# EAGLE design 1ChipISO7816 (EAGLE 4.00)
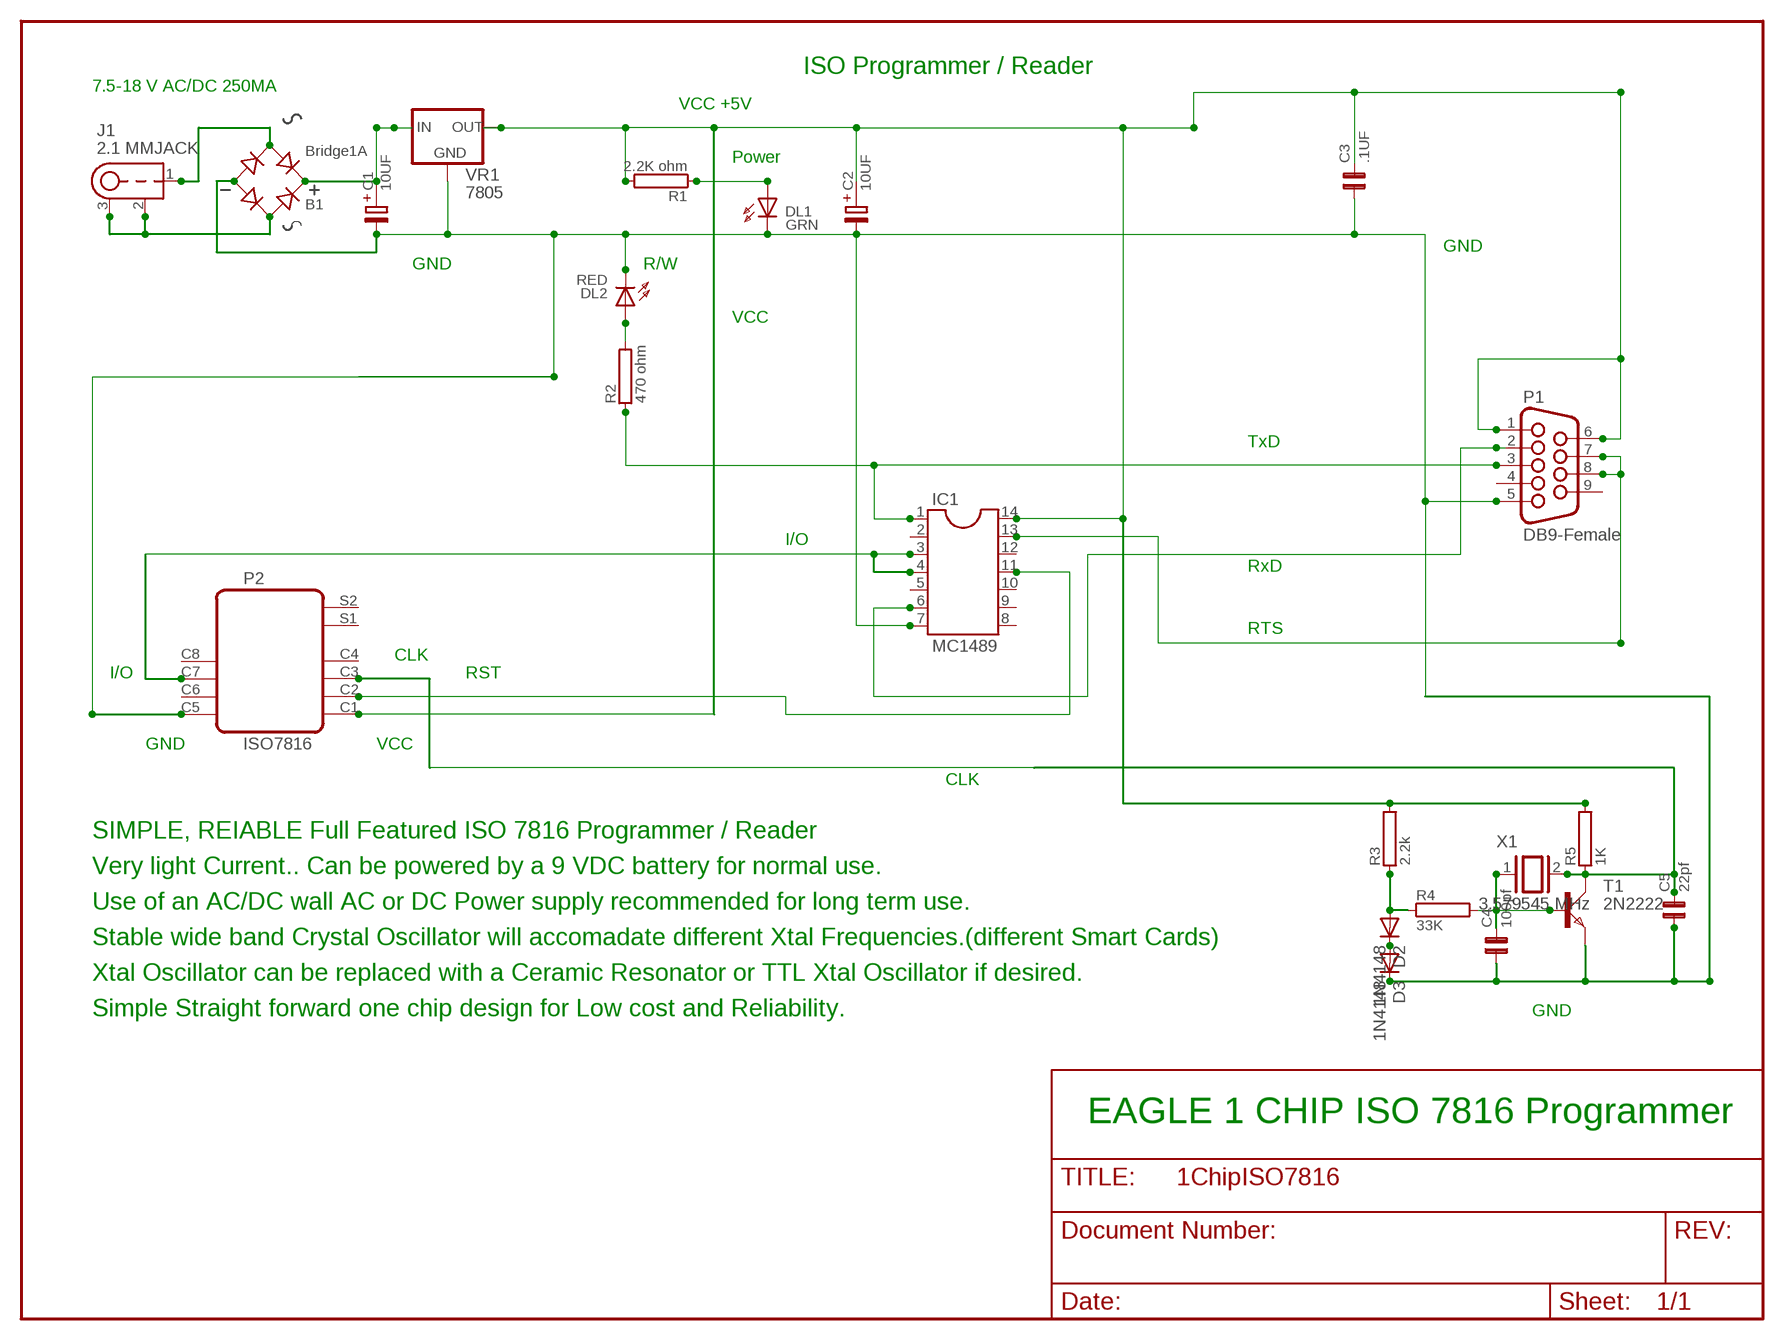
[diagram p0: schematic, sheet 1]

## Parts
B1  Bridge1A  B-DIL  [B-DIL]
C1  10UF  P128-35  [P128-35]
C2  10UF  P128-35  [P128-35]
C3  .1UF  C2,5  [C2,5-4]
C4  100pf  C2,5  [C2,5-4]
C5  22pf  C2,5  [C2,5-4]
D2  1N4148  [DO35-10]
D3  1N4148  [DO35-10]
DL1  GRN  LED5  [LED5]
DL2  RED  LED5  [LED5]
IC1  MC1489  DIL14  [DIL14]
J1  2.1 MMJACK  2MMJACK  [255SB]
P1  DB9-Female  F09H  [F09H]
P2  ISO7816  14P  [14P]
R1  2.2K ohm  0309/10@2  [0309/10@2]
R2  470 ohm  0309/10@2  [0309/10@2]
R3  2.2k  0309/10@2  [0309/10@2]
R4  33K  0309/10  [0309/10]
R5  1K  0309/10@2  [0309/10@2]
T1  2N2222  [TO18A]
VR1  7805  78XXL  [78XXL]
X1  3.579545 MHz  XTAL  [Q]

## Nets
+12V: B1.+ C1.+ VR1.E(IN)
CLK: C5.2 P2.C3 R5.1 T1.C X1.2
I/O: IC1.3 IC1.4 P2.C7
N$1: B1.- C1.- C2.- C3.1 C4.1 C5.1 D3.K(C) DL1.K DL2.K IC1.7 P1.5 P2.C5 T1.E VR1.GND
N$2: B1.AC1 J1.2 J1.3
N$3: D2.A R3.1 R4.1
N$4: IC1.6 P1.2
N$6: IC1.13 P1.7 P1.8
N$8: IC1.1 P1.3 R2.1
N$9: D2.K(C) D3.A
N$22: DL1.A R1.1
N$24: DL2.A R2.2
N$25: C4.2 R4.2 T1.B X1.1
N$28: B1.AC2 J1.1
OUT: C2.+ C3.2 IC1.14 P1.1 P1.6 P2.C1 R1.2 R3.2 R5.2 VR1.A(OUT)
RST: IC1.11 P2.C2
Unconnected: IC1.2 IC1.5 IC1.8 IC1.9 IC1.10 IC1.12 P1.4 P1.9 P2.C4 P2.C6 P2.C8 P2.S1 P2.S2

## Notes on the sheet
- ISO Programmer / Reader
- 7.5-18 V AC/DC 250MA
- VCC +5V
- Power
- GND
- GND | R/W
- VCC
- TxD
- I/O
- RxD
- RTS
- CLK
- I/O | RST
- GND | VCC
- CLK
- SIMPLE, REIABLE Full Featured ISO 7816 Programmer / Reader
- Very light Current.. Can be powered by a 9 VDC battery for normal use.
- Use of an AC/DC wall AC or DC Power supply recommended for long term use.
- Stable wide band Crystal Oscillator will accomadate different Xtal Frequencies.(different Smart Cards)
- Xtal Oscillator can be replaced with a Ceramic Resonator or TTL Xtal Oscillator if desired.
- Simple Straight forward one chip design for Low cost and Reliability. | GND
- EAGLE 1 CHIP ISO 7816 Programmer

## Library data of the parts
B1 = RECTIF:B-DIL
C1 C2 = CAP-TANT:P128-35
C3-C5 = CAP:C2,5
D2 D3 = diode:1N4148: DIODE
DL1 DL2 = LED:LED5
IC1 = dil:DIL14: SOCKET DIL14
J1 = PWRJACK:2MMJACK
P1 = D-SUB:F09H
P2 = CON-ISO:14P
R1-R3 R5 = R:0309/10@2
R4 = R:0309/10
T1 = transistor-small-signal:2N2222: NPN TRANSISTOR
VR1 = V-REG:78XXL
X1 = SPECIAL:XTAL

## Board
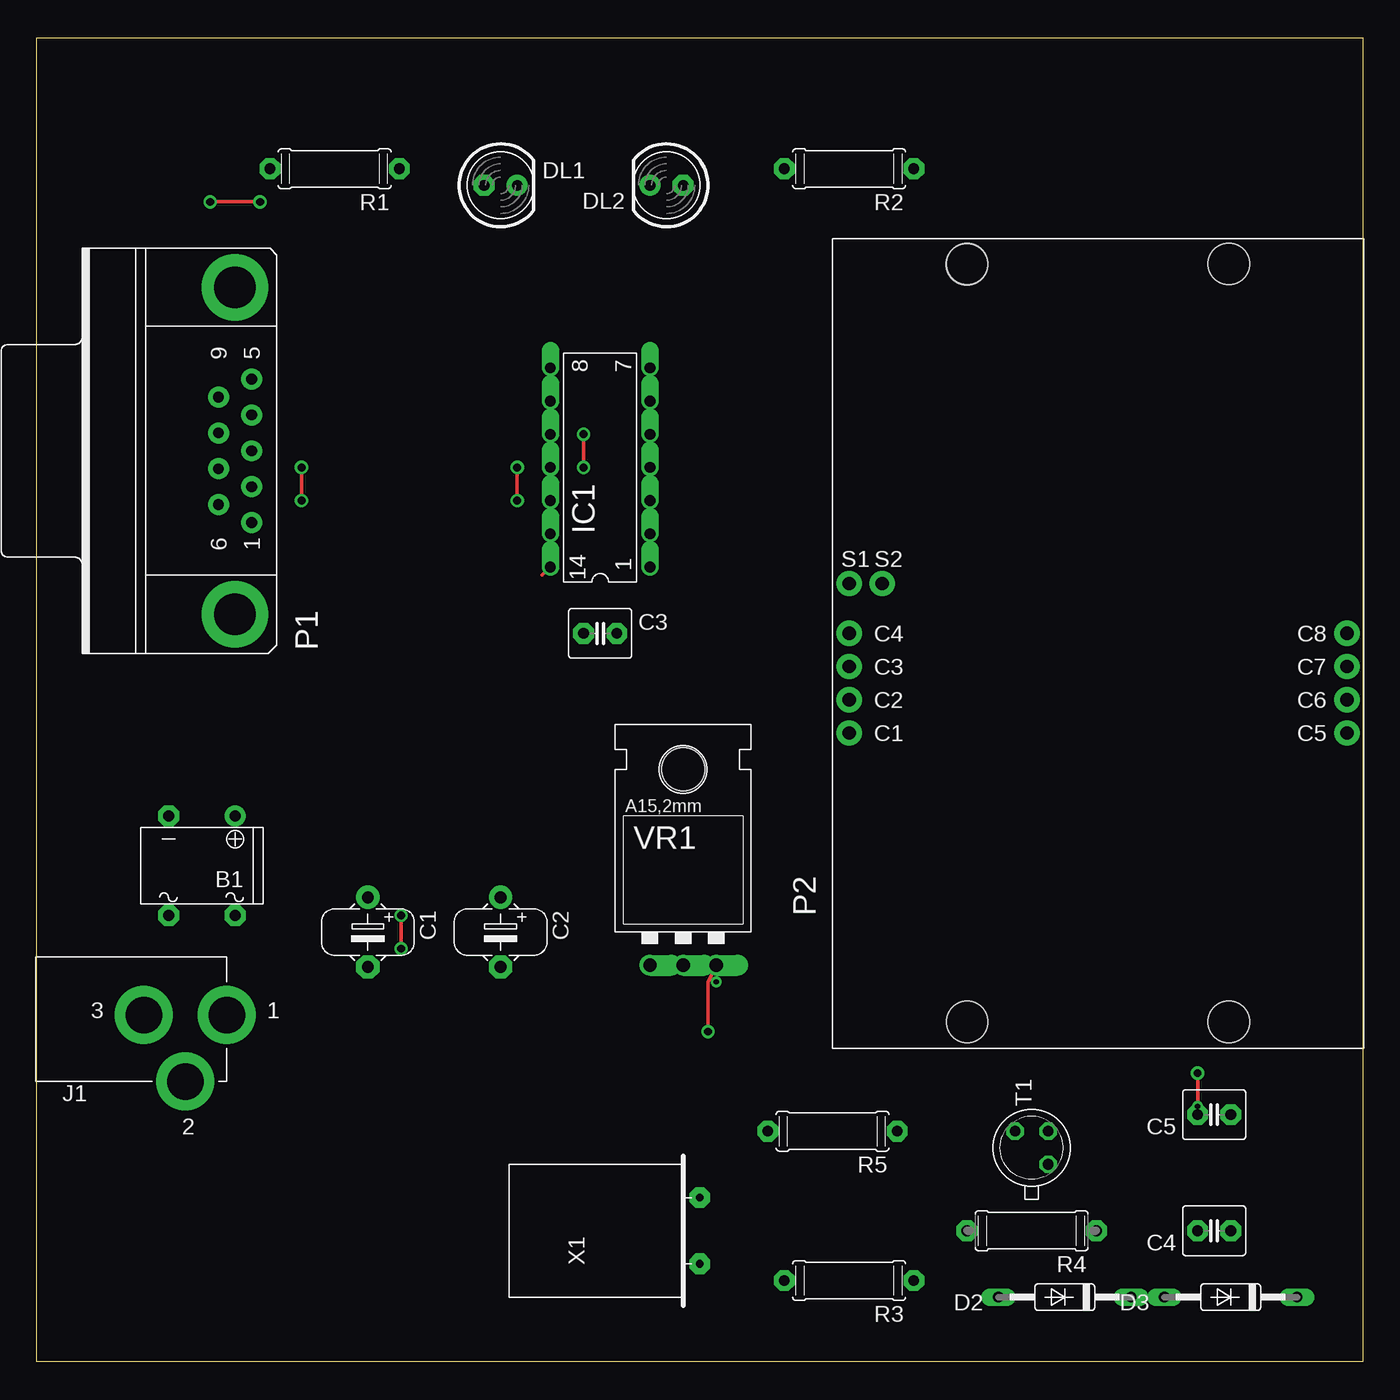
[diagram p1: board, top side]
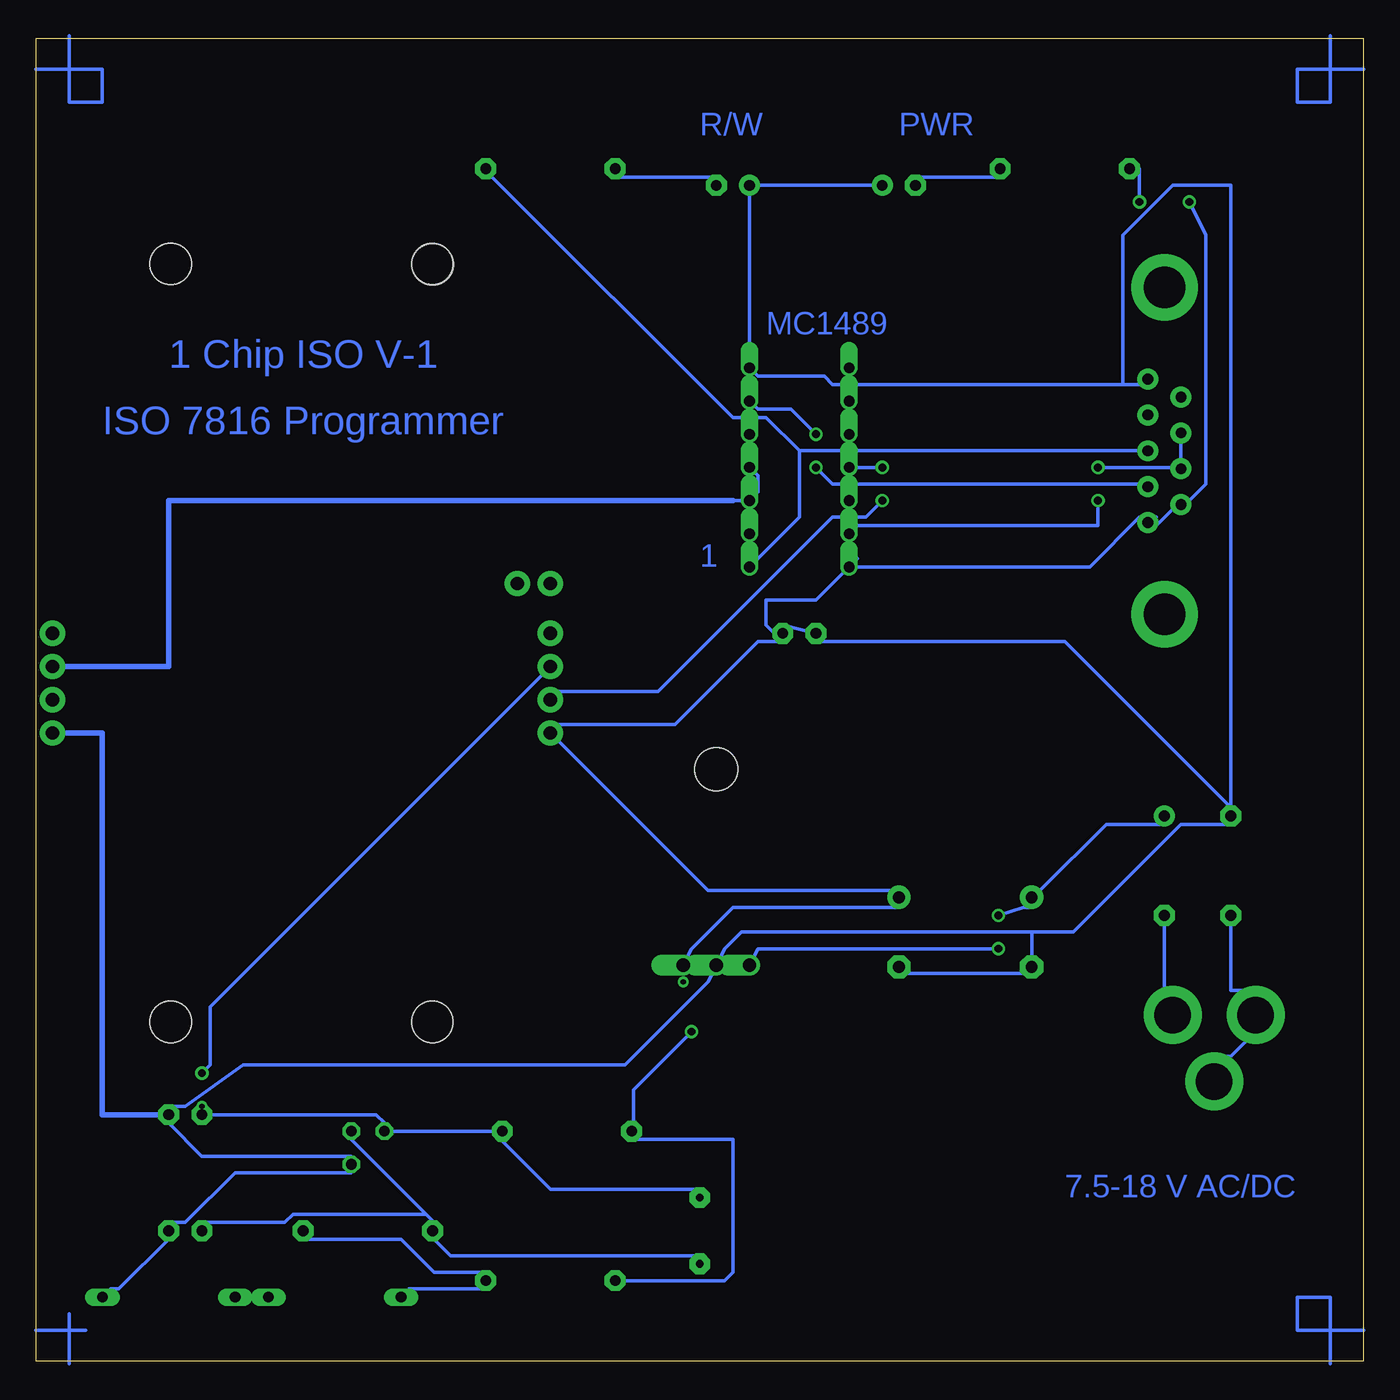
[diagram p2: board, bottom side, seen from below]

Size 101.58 x 101.27 mm. Coordinates in mm from the lower left corner, seen from the top.
Outline: 0,0 101.58,0 101.58,101.27 0,101.27 0,0
Copper layers used: Top, Bottom

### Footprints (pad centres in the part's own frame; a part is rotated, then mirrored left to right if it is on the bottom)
B-DIL = drill 0.813 pad 1.6 round: + -2.54,-3.81 | drill 0.813 pad 1.6 octagon: - 2.54,-3.81; AC1 2.54,3.81; AC2 -2.54,3.81
P128-35 = drill 0.914 pad 1.778 round: + -2.667,0 | drill 0.914 pad 1.778 octagon: - 2.667,0
C2,5-4 = drill 0.813 pad 1.6 octagon: 1 -1.27,0; 2 1.27,0
DO35-10 = drill 0.813 long: A 5.08,0; K -5.08,0
LED5 = drill 0.813 pad 1.6 octagon: A -1.27,0 | drill 0.813 pad 1.6 round: K 1.27,0
DIL14 = drill 0.813 offset: 1 -7.62,-3.81; 2 -5.08,-3.81; 3 -2.54,-3.81; 4 0,-3.81; 5 2.54,-3.81; 6 5.08,-3.81; 7 7.62,-3.81; 8 7.62,3.81; 9 5.08,3.81; 10 2.54,3.81; 11 0,3.81; 12 -2.54,3.81; 13 -5.08,3.81; 14 -7.62,3.81
255SB = drill 2.794 pad 4.445 round: 1 3.175,0; 2 0,-5.08; 3 -3.175,0
F09H = drill 0.813 pad 1.6 round: 1 -5.486,-1.27; 2 -2.743,-1.27; 3 0,-1.27; 4 2.743,-1.27; 5 5.486,-1.27; 6 -4.115,1.27; 7 -1.372,1.27; 8 1.372,1.27; 9 4.115,1.27 | drill 3.175 pad 5.08 round: 10 -12.497,0; 11 12.497,0
14P = drill 1.016 pad 1.93 round: C1 -19.05,-6.35; C2 -19.05,-3.81; C3 -19.05,-1.27; C4 -19.05,1.27; C5 19.05,-6.35; C6 19.05,-3.81; C7 19.05,-1.27; C8 19.05,1.27; S1 -19.05,5.08; S2 -16.51,5.08 | hole 3.175: -10.008,-28.473; 10.008,-28.473; 10.008,29.54; -10.033,29.515; -10.008,29.54
0309/10@2 = drill 0.813 pad 1.6 octagon: 1 -4.953,0; 2 4.953,0
0309/10 = drill 0.813 pad 1.6 octagon: 1 -4.953,0; 2 4.953,0
TO18A = drill 0.813 octagon: B 1.27,-1.27; C 1.27,1.27; E -1.27,-1.27
78XXL = drill 1.016 pad 1.626 offset: A 2.54,-3.81; E -2.54,-3.81; GND 0,-3.81 | hole 3.302: 0,11.176
Q = drill 0.61 pad 1.6 octagon: 1 -2.54,-7.62; 2 2.54,-7.62

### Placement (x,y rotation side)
B1  12.69,37.94 180 top
C1  25.39,32.86 270 top
C2  35.55,32.86 270 top
C3  43.17,55.72 0 top
C4  90.17,10 180 top
C5  90.17,18.89 180 top
D2  78.73,4.92 180 top
D3  91.44,4.92 180 top
DL1  35.55,90 0 top
DL2  48.25,90 180 top
IC1  43.17,68.41 90 top
J1  11.42,26.51 0 top
P1  15.23,69.68 90 top
P2  81.28,54.45 0 top
R1  22.86,91.27 180 top
R2  62.22,91.27 180 top
R3  62.22,6.18 180 top
R4  76.2,10 180 top
R5  60.95,17.62 180 top
T1  76.2,16.35 90 top
VR1  49.52,34.12 0 top
X1  43.17,10 90 top

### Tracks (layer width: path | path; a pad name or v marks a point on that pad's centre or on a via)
+12V  (via drill 0.61)
  Top 0.254: v27.94,34.12 v27.94,31.59
  Bottom 0.254: B1.+ 15.23,41.11 19.68,41.11 24.76,36.03 C1.+ 25.39,34.76 26.03,34.76 v27.94,34.12 | v27.94,31.59 46.35,31.59 VR1.E
CLK  (via drill 0.41, 0.61)
  Top 0.254: C5.2 v88.9,19.52 v88.9,22.06
  Bottom 0.254: X1.2 50.79,13.17 62.22,13.17 66.04,16.98 R5.1 T1.C 74.93,18.25 75.56,18.89 C5.2 | v88.9,22.06 88.26,22.7 88.26,27.14 P2.C3
I/O
  Bottom 0.254: IC1.4 46.35,67.78 46.35,66.51 IC1.3 48.25,65.88
  Bottom 0.406: 48.25,65.88 91.44,65.88 91.44,53.18 P2.C7
N$1
  Bottom 0.254: DL1.K DL2.K IC1.7 46.35,75.4 41.27,75.4 40.63,74.77 18.41,74.77 | 18.41,74.77 17.14,74.77 P1.5 | D3.K 95.88,5.55 95.25,5.55 91.44,9.36 C4.1 91.44,10.63 90.17,10.63 86.36,14.44 77.47,14.44 T1.E 77.47,15.71 88.9,15.71 91.44,18.25 C5.1 91.44,19.52 90.17,19.52 85.72,22.7 56.51,22.7 50.16,29.05 VR1.GND 48.89,31.59 47.62,32.86 25.39,32.86 | C2.- 34.92,29.68 26.03,29.68 C1.- 25.39,32.86 | 25.39,32.86 22.22,32.86 13.96,41.11 10.15,41.11 B1.- 10.15,42.38 | C3.1 44.45,56.35 | C3.1 41.9,56.35 | 10.15,42.38 22.86,55.08 41.9,55.08 C3.1 | 18.41,74.77 18.41,86.19 14.6,90 10.15,90 10.15,42.38
  Bottom 0.406: P2.C5 96.52,48.09 96.52,18.89 C5.1
N$2
  Bottom 0.254: B1.AC1 10.15,28.41 8.88,28.41 J1.3 8.88,24.6 10.15,23.33 10.79,23.33 J1.2
N$3
  Top 0.254: R3.1 67.31,6.82
  Bottom 0.254: D2.A 73.02,5.55 67.31,5.55 R3.1 67.31,6.82 71.12,6.82 73.66,9.36 81.28,9.36 R4.1
N$4  (via drill 0.61)
  Top 0.254: v41.9,68.41 v41.9,70.95
  Bottom 0.254: v41.9,70.95 43.81,72.86 46.35,72.86 IC1.6 | v41.9,68.41 40.63,67.14 17.14,67.14 P1.2
N$6  (via drill 0.61)
  Top 0.254: v20.32,68.41 v20.32,65.88
  Bottom 0.254: v20.32,65.88 20.32,63.97 38.73,63.97 IC1.13 | v20.32,68.41 14.6,68.41 P1.7 P1.8
N$7  (via drill 0.41)
  other vias: 52.06,29.05
N$8
  Bottom 0.254: 43.17,69.68 43.17,64.6 IC1.1 | P1.3 43.17,69.68 | 43.17,69.68 45.71,72.22 48.25,72.22 66.67,90.64 67.31,90.64 R2.1
N$9
  Bottom 0.254: D2.K D3.A
N$10
  Bottom 0.254: 101.59,98.89 96.52,98.89 96.52,96.35 99.06,96.35 99.06,101.43
N$11
  Bottom 0.254: 101.59,2.38 99.06,2.38 | 99.06,2.38 99.06,-0.17 | 99.06,3.65 99.06,2.38 | 99.06,2.38 97.79,2.38
N$12
  Bottom 0.254: -0.01,2.38 5.08,2.38 5.08,4.92 2.54,4.92 2.54,-0.17
N$13
  Bottom 0.254: -0.01,98.89 5.08,98.89 5.08,96.35 2.54,96.35 2.54,101.43
N$22
  Bottom 0.254: R1.1 27.94,90.64 34.28,90.64 DL1.A
N$24
  Bottom 0.254: DL2.A 49.52,90.64 57.14,90.64 R2.2
N$25
  Bottom 0.254: 71.75,11.27 71.12,10.63 R4.2 71.12,9.36 69.84,8.09 50.79,8.09 X1.1 | 71.75,11.27 77.47,16.98 T1.B | 71.75,11.27 81.91,11.27 82.55,10.63 88.9,10.63 C4.2
N$28
  Bottom 0.254: B1.AC2 15.23,28.41 J1.1
OUT  (via drill 0.61)
  Top 0.254: v51.43,25.23 51.43,29.05 VR1.A | IC1.14 38.73,60.16 | v13.33,88.73 v17.14,88.73
  Bottom 0.254: R3.2 48.89,6.18 48.25,6.82 48.25,16.98 55.88,16.98 R5.2 55.88,18.25 55.88,20.79 v51.43,25.23 | VR1.A 51.43,31.59 48.25,34.76 35.55,34.76 C2.+ 36.19,36.03 50.16,36.03 P2.C1 61.59,48.73 52.7,48.73 46.35,55.08 44.45,55.08 C3.2 45.08,55.72 45.71,56.35 45.71,58.26 41.9,58.26 IC1.14 | IC1.14 38.73,61.43 | P1.1 15.87,64.6 | v17.14,88.73 17.14,91.27 R1.2 | v13.33,88.73 12.06,86.19 12.06,67.14 13.33,65.88 P1.6 14.6,65.24 15.87,63.97 P1.1 | P1.1 17.14,64.6 20.95,60.8 IC1.14
RST  (via drill 0.61)
  Top 0.254: v36.82,65.88 v36.82,68.41
  Bottom 0.254: v36.82,65.88 38.09,64.6 40.63,64.6 53.97,51.27 61.59,51.27 P2.C2 | v36.82,68.41 IC1.11

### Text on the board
Bottom: PWR | R/W | MC1489 | 1 Chip ISO V-1 | ISO 7816 Programmer | 1 | 7.5-18 V AC/DC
